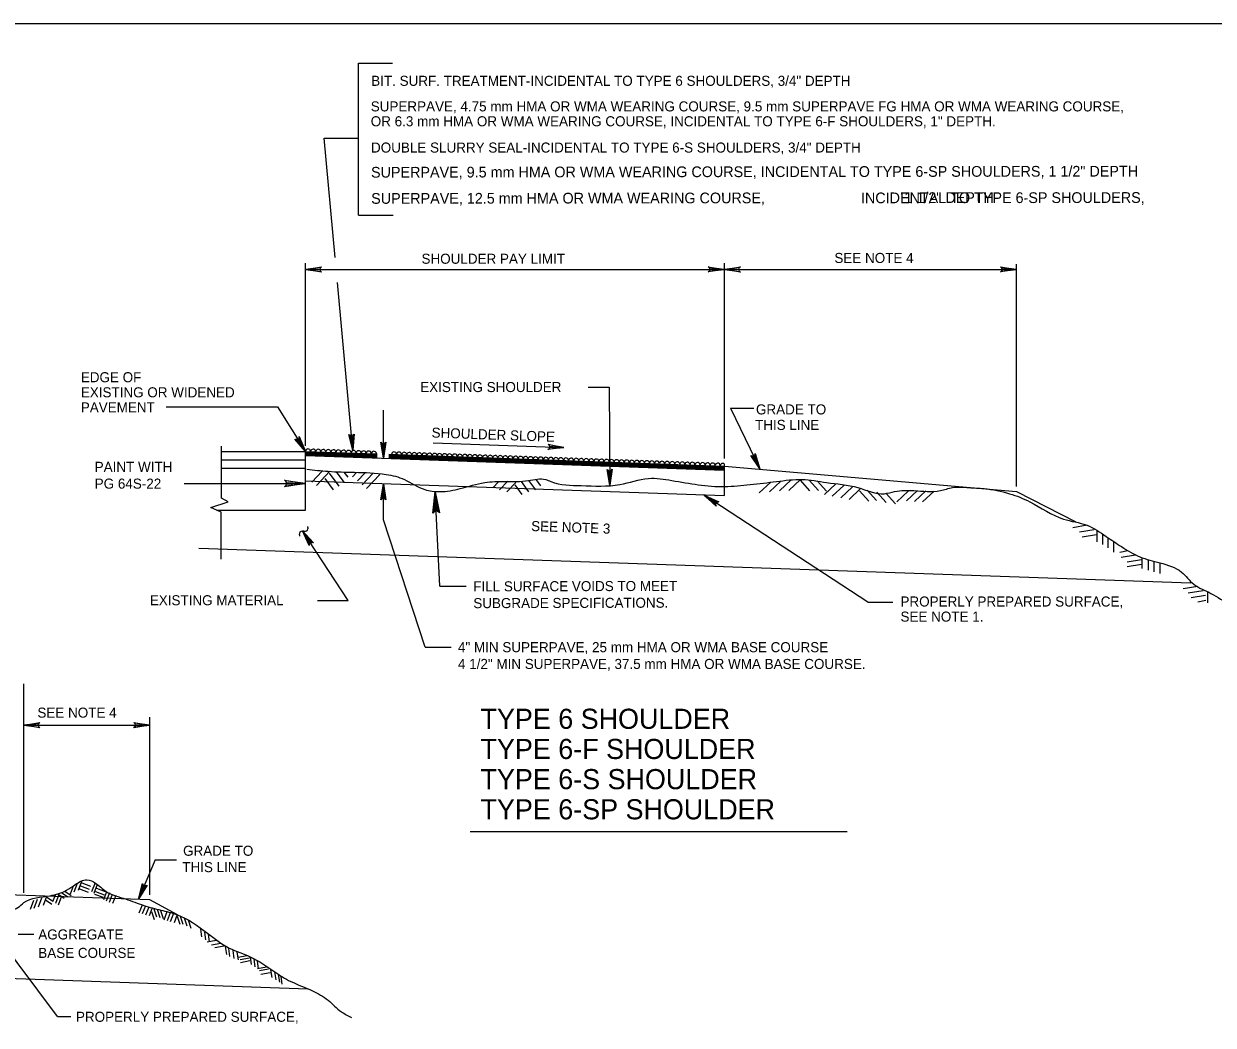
# Model space of a CAD drawing. Extents: x 638216 to 639962, y 297510 to 299292.
# Drawn here: x 638435.2 to 638790, y 298384.5 to 298683.2 of the extents above; entities that cross this region are included whole.
import ezdxf

# ---------------------------------------------------------------- set-up
doc = ezdxf.new("R2010")
doc.units = 0
for name, color, linetype in [('1', 7, 'Continuous'), ('2', 7, 'Continuous'), ('3', 7, 'Continuous')]:
    doc.layers.add(name, color=color, linetype=linetype)

msp = doc.modelspace()

# ---------------------------------------------------------------- linework, layer by layer
at = {"layer": '1'}
for points in [[(639041.88, 298119.24), (639041.88, 298683.24), (638255.88, 298683.24), (638255.88, 298119.24), (639041.88, 298119.24), (639041.88, 298145.6), (638841.88, 298145.6), (638841.88, 298210.28), (639041.88, 298210.28), (639041.88, 298239.24), (638841.88, 298239.24), (638841.88, 298119.24), (638920.69, 298119.24), (638920.69, 298145.6), (638920.69, 298119.24), (638997.69, 298119.24), (638997.69, 298145.6), (638997.69, 298133.28), (639041.88, 298133.28)], [(639041.88, 298119.24), (639041.88, 298683.24), (638255.88, 298683.24), (638255.88, 298119.24), (639041.88, 298119.24), (639041.88, 298145.6), (638841.88, 298145.6), (638841.88, 298210.28), (639041.88, 298210.28), (639041.88, 298239.24), (638841.88, 298239.24), (638841.88, 298119.24), (638920.69, 298119.24), (638920.69, 298145.6), (638920.69, 298119.24), (638997.69, 298119.24), (638997.69, 298145.6), (638997.69, 298133.28), (639041.88, 298133.28)], [(638513.28, 298546.86), (638513.5, 298546.43), (638519.27, 298546.11), (638513.28, 298546.86), (638512.97, 298547.13), (638519.27, 298546.11), (638513.5, 298545.83), (638513.29, 298545.4), (638519.27, 298546.11), (638512.97, 298545.11), (638513.29, 298545.4)], [(638557.48, 298537.59), (638557.9, 298537.84), (638557.93, 298543.62), (638557.48, 298537.59), (638557.23, 298537.27), (638557.93, 298543.62), (638558.5, 298537.87), (638558.94, 298537.69), (638557.93, 298543.62), (638559.25, 298537.38), (638558.94, 298537.69)]]:
    msp.add_lwpolyline(points, dxfattribs=at)
at = {"layer": '2'}
for p, q in [((638535.05, 298626.15), (638535.05, 298671.46)), ((638535.05, 298671.46), (638545.24, 298671.46)), ((638524.82, 298649.13), (638535.05, 298649.13)), ((638528.1, 298613.48), (638524.82, 298649.13)), ((638535.05, 298626.15), (638545.43, 298626.15)), ((638519.27, 298557.32), (638519.27, 298611.79)), ((638519.27, 298609.96), (638644.18, 298609.96)), ((638644.2, 298553.53), (638644.2, 298611.85)), ((638644.2, 298609.96), (638731.36, 298609.96)), ((638731.36, 298545.18), (638731.36, 298611.57)), ((638533.4, 298556.03), (638528.78, 298606.11)), ((638603.56, 298574.82), (638609.79, 298574.82)), ((638609.79, 298574.82), (638610.07, 298545.57)), ((638477.72, 298568.99), (638510.86, 298568.99)), ((638510.86, 298568.99), (638519.27, 298555.68)), ((638542.49, 298553.62), (638542.49, 298568.01)), ((638646.01, 298568.53), (638653, 298568.53)), ((638646.01, 298568.53), (638654.83, 298550.46)), ((638494.19, 298541.7), (638494.19, 298557.23)), ((638557.37, 298558.26), (638596.36, 298556.87)), ((638494.27, 298555.68), (638519.27, 298555.68)), ((638494.27, 298553.18), (638519.27, 298553.18)), ((638519.24, 298554.7), (638540.67, 298553.96)), ((638519.24, 298554.63), (638540.67, 298553.88)), ((638519.24, 298554.55), (638540.67, 298553.8)), ((638519.24, 298554.43), (638644.15, 298550.07)), ((638519.27, 298538.18), (638519.27, 298555.68)), ((638519.27, 298555.68), (638540.67, 298554.93)), ((638519.28, 298554.83), (638540.67, 298554.09)), ((638519.28, 298554.73), (638540.67, 298553.98)), ((638519.3, 298554.93), (638540.67, 298554.19)), ((638519.33, 298555.54), (638540.67, 298554.79)), ((638519.33, 298555.46), (638540.67, 298554.72)), ((638519.33, 298555.39), (638540.67, 298554.64)), ((638519.33, 298555.24), (638540.67, 298554.49)), ((638519.33, 298555.21), (638540.67, 298554.47)), ((638519.33, 298555.13), (638540.67, 298554.39)), ((638519.33, 298555.06), (638540.67, 298554.31)), ((638544.04, 298553.69), (638644.1, 298550.19)), ((638544.08, 298554.81), (638644.2, 298551.31)), ((638544.08, 298554.67), (638644.25, 298551.18)), ((638544.08, 298554.6), (638644.25, 298551.1)), ((638544.08, 298554.52), (638644.25, 298551.03)), ((638544.08, 298554.37), (638644.25, 298550.87)), ((638544.08, 298554.35), (638644.25, 298550.85)), ((638544.08, 298554.27), (638644.25, 298550.77)), ((638544.08, 298554.19), (638644.25, 298550.7)), ((638544.08, 298554.07), (638644.23, 298550.57)), ((638544.08, 298553.97), (638644.2, 298550.47)), ((638544.08, 298553.86), (638644.2, 298550.37)), ((638544.08, 298553.84), (638644.15, 298550.34)), ((638544.08, 298553.76), (638644.15, 298550.27)), ((638494.27, 298550.68), (638519.27, 298550.68)), ((638524.26, 298549.82), (638521.17, 298546.55)), ((638526.51, 298549.74), (638522.53, 298545.54)), ((638526.35, 298549.21), (638529.19, 298545.35)), ((638528.45, 298549.54), (638530.68, 298546.51)), ((638530.71, 298549.53), (638531.86, 298547.97)), ((638534.37, 298549.3), (638533.23, 298548.1)), ((638537, 298549.22), (638534.78, 298546.88)), ((638644.2, 298551.31), (638644.2, 298551.92)), ((638644.2, 298542.56), (638644.2, 298551.31)), ((638644.2, 298551.31), (638731.36, 298543.69)), ((638483.09, 298546.11), (638519.27, 298546.11)), ((638519.26, 298546.92), (638644.2, 298542.56)), ((638525.02, 298547.64), (638527.55, 298544.21)), ((638539.36, 298549.07), (638536.19, 298545.73)), ((638541.46, 298548.79), (638537.48, 298544.59)), ((638542.49, 298535.26), (638542.49, 298546.03)), ((638576.91, 298546.72), (638575.1, 298544.81)), ((638579.58, 298546.82), (638577.14, 298544.24)), ((638581.98, 298546.42), (638579.36, 298543.66)), ((638581.65, 298545.67), (638583.74, 298542.82)), ((638583.54, 298546.68), (638585.78, 298543.64)), ((638585.78, 298547.04), (638587.87, 298544.19)), ((638588.05, 298547.16), (638589.37, 298545.37)), ((638658.06, 298546.52), (638654.6, 298543.29)), ((638661.08, 298546.85), (638657.62, 298543.62)), ((638664.16, 298547.18), (638660.7, 298543.94)), ((638666.93, 298547.29), (638663.47, 298544.05)), ((638666.81, 298547.06), (638669.61, 298543.95)), ((638669.46, 298547.11), (638672.26, 298544)), ((638671.87, 298546.88), (638674.67, 298543.77)), ((638677.31, 298545.9), (638674.03, 298542.84)), ((638559.36, 298515.52), (638557.93, 298543.62)), ((638687, 298510.73), (638638.18, 298542.65)), ((638679.84, 298545.52), (638676.38, 298542.29)), ((638682.4, 298545.07), (638678.94, 298541.83)), ((638684.85, 298544.61), (638681.39, 298541.38)), ((638684.52, 298543.93), (638687.32, 298540.82)), ((638686.78, 298544.16), (638689.58, 298541.05)), ((638689.72, 298543.51), (638692.52, 298540.4)), ((638692.48, 298543.15), (638695.29, 298540.05)), ((638699.07, 298543.82), (638695.61, 298540.59)), ((638701.83, 298544.02), (638698.54, 298540.95)), ((638704.35, 298543.95), (638700.89, 298540.72)), ((638706.8, 298543.85), (638703.34, 298540.62)), ((638731.36, 298543.69), (638749.09, 298534.67)), ((638492.67, 298538.18), (638519.27, 298538.18)), ((638494.12, 298523.51), (638494.12, 298537.55)), ((638554.92, 298497.31), (638542.49, 298535.26)), ((638531.96, 298511.18), (638518.35, 298531.99)), ((638752.48, 298533.64), (638748.18, 298532.93)), ((638754.47, 298532.32), (638750.17, 298531.62)), ((638755.29, 298531.85), (638755.29, 298528.74)), ((638755.19, 298530.78), (638750.89, 298530.07)), ((638757.04, 298531.01), (638757.04, 298527.9)), ((638758.58, 298530.04), (638758.58, 298526.93)), ((638760.27, 298528.71), (638760.27, 298525.6)), ((638487.47, 298526.79), (638783.31, 298516.46)), ((638762.17, 298525.62), (638764.57, 298526.11)), ((638766.87, 298524.77), (638762.57, 298524.07)), ((638768.65, 298521.91), (638764.35, 298521.21)), ((638768.67, 298523.32), (638764.37, 298522.61)), ((638768.78, 298523.82), (638768.78, 298520.71)), ((638770.58, 298523.39), (638770.58, 298520.28)), ((638772.29, 298522.82), (638772.29, 298519.71)), ((638774.09, 298522.37), (638774.09, 298519.27)), ((638559.36, 298515.52), (638567.16, 298515.52)), ((638785.4, 298515.42), (638781.1, 298514.72)), ((638787.07, 298514.09), (638782.57, 298513.36)), ((638788.33, 298513.8), (638788.33, 298510.53)), ((638522.88, 298511.18), (638531.96, 298511.18)), ((638687, 298510.73), (638694.44, 298510.73)), ((638787.71, 298512.74), (638783.41, 298512.03)), ((638785.47, 298510.83), (638787.86, 298511.32)), ((638554.92, 298497.31), (638562.72, 298497.31)), ((638435.23, 298424.01), (638435.23, 298486.38)), ((638472.83, 298423.43), (638472.83, 298476.36)), ((638435.23, 298474.02), (638472.81, 298474.02)), ((638568.35, 298442.28), (638680.79, 298442.28)), ((638474.43, 298433.88), (638469.47, 298422.14)), ((638474.43, 298433.88), (638480.77, 298433.88)), ((638449.96, 298426.01), (638449.04, 298423.59)), ((638451.17, 298426.83), (638450.16, 298424.15)), ((638452.41, 298427.4), (638451.39, 298424.72)), ((638451.88, 298425.17), (638454.45, 298424.22)), ((638452.13, 298426.06), (638454.7, 298425.11)), ((638452.58, 298426.98), (638455.16, 298426.02)), ((638456.46, 298427.01), (638455.45, 298424.33)), ((638457.14, 298426.48), (638456.12, 298423.8)), ((638456.92, 298425.35), (638459.5, 298424.4)), ((638408.83, 298424.26), (638472.68, 298422.03)), ((638438.1, 298421.67), (638437.08, 298418.99)), ((638439.19, 298422.06), (638438.18, 298419.37)), ((638440.5, 298422.41), (638439.48, 298419.73)), ((638441.98, 298422.91), (638440.96, 298420.22)), ((638441.69, 298421.95), (638443.56, 298420.63)), ((638442.02, 298422.8), (638443.89, 298421.49)), ((638444.65, 298423.47), (638443.82, 298421.29)), ((638445.65, 298423.55), (638444.63, 298420.86)), ((638445.4, 298423.71), (638447.27, 298422.39)), ((638446.51, 298422.97), (638445.49, 298420.29)), ((638446.45, 298424.14), (638448.32, 298422.82)), ((638447.5, 298424.47), (638449.36, 298423.16)), ((638456.32, 298423.62), (638458.9, 298422.67)), ((638456.61, 298424.4), (638459.18, 298423.45)), ((638459.89, 298424.31), (638458.97, 298421.87)), ((638460.76, 298423.96), (638459.83, 298421.52)), ((638461.62, 298423.51), (638460.7, 298421.07)), ((638462.65, 298423.25), (638461.72, 298420.81)), ((638472.68, 298422.03), (638480.95, 298417.49)), ((638470.5, 298420.35), (638469.57, 298417.91)), ((638471.49, 298420.12), (638470.57, 298417.69)), ((638472.49, 298419.77), (638471.56, 298417.33)), ((638473.54, 298419.55), (638472.62, 298417.11)), ((638473.32, 298418.42), (638474.09, 298416.02)), ((638474.01, 298419.24), (638474.78, 298416.84)), ((638475.03, 298419.08), (638475.8, 298416.68)), ((638476.03, 298418.73), (638476.8, 298416.33)), ((638477.92, 298418.33), (638476.99, 298415.89)), ((638478.91, 298418.06), (638477.98, 298415.62)), ((638445.25, 298387.11), (638423.56, 298416.16)), ((638479.84, 298417.8), (638478.92, 298415.36)), ((638480.95, 298417.49), (638480.03, 298415.06)), ((638480.95, 298417.01), (638481.72, 298414.61)), ((638481.88, 298417.08), (638482.65, 298414.67)), ((638483.09, 298416.56), (638483.86, 298414.16)), ((638484.26, 298415.9), (638485.03, 298413.49)), ((638433.58, 298411.66), (638438.18, 298411.66)), ((638487.89, 298413.17), (638488.24, 298410.85)), ((638489.09, 298412.29), (638489.44, 298409.97)), ((638490.18, 298411.69), (638490.53, 298409.37)), ((638492.65, 298409.82), (638489.9, 298409.29)), ((638493.99, 298408.91), (638491.24, 298408.38)), ((638494.98, 298408.1), (638492.23, 298407.57)), ((638495.29, 298407.95), (638495.65, 298405.63)), ((638496.25, 298407.36), (638496.6, 298405.03)), ((638497.55, 298406.79), (638497.9, 298404.46)), ((638498.78, 298406.33), (638499.14, 298404)), ((638501.85, 298405.24), (638499.1, 298404.71)), ((638502.52, 298404.53), (638499.77, 298404.01)), ((638502.74, 298404.92), (638503.09, 298402.59)), ((638503.83, 298404.25), (638504.18, 298401.92)), ((638335.27, 298401.82), (638519.95, 298395.37)), ((638502.63, 298403.69), (638499.88, 298403.16)), ((638504.82, 298403.62), (638505.17, 298401.29)), ((638507.64, 298401.82), (638504.89, 298401.29)), ((638508.24, 298401.22), (638505.49, 298400.69)), ((638508.84, 298401.04), (638509.19, 298398.71)), ((638510, 298400.41), (638510.36, 298398.08)), ((638508.7, 298400.16), (638505.95, 298399.63)), ((638511.13, 298399.66), (638511.48, 298397.34)), ((638511.87, 298399.07), (638512.22, 298396.74)), ((638445.25, 298387.11), (638449.27, 298387.11))]:
    msp.add_line(p, q, dxfattribs=at)
for points in [[(638523.81, 298609.39), (638523.64, 298609.72), (638519.27, 298609.96), (638523.81, 298609.39), (638524.05, 298609.19), (638519.27, 298609.96), (638523.64, 298610.18), (638523.8, 298610.5), (638519.27, 298609.96), (638524.05, 298610.72), (638523.8, 298610.5)], [(638639.64, 298610.53), (638639.81, 298610.2), (638644.18, 298609.96), (638639.64, 298610.53), (638639.4, 298610.73), (638644.18, 298609.96), (638639.81, 298609.74), (638639.65, 298609.42), (638644.18, 298609.96), (638639.4, 298609.2), (638639.65, 298609.42)], [(638648.74, 298609.39), (638648.57, 298609.72), (638644.2, 298609.96), (638648.74, 298609.39), (638648.97, 298609.19), (638644.2, 298609.96), (638648.56, 298610.18), (638648.72, 298610.5), (638644.2, 298609.96), (638648.97, 298610.72), (638648.72, 298610.5)], [(638726.82, 298610.53), (638726.99, 298610.2), (638731.36, 298609.96), (638726.82, 298610.53), (638726.59, 298610.73), (638731.36, 298609.96), (638727, 298609.74), (638726.84, 298609.42), (638731.36, 298609.96), (638726.59, 298609.2), (638726.84, 298609.42)], [(638517.33, 298559.82), (638517.14, 298559.5), (638519.27, 298555.68), (638517.33, 298559.82), (638517.37, 298560.12), (638519.27, 298555.68), (638516.76, 298559.25), (638516.4, 298559.22), (638519.27, 298555.68), (638516.08, 298559.31), (638516.4, 298559.22)], [(638533.55, 298560.61), (638533.24, 298560.41), (638533.4, 298556.03), (638533.55, 298560.61), (638533.73, 298560.86), (638533.4, 298556.03), (638532.79, 298560.36), (638532.45, 298560.49), (638533.4, 298556.03), (638532.21, 298560.72), (638532.45, 298560.49)], [(638543.06, 298558.16), (638542.73, 298557.99), (638542.49, 298553.62), (638543.06, 298558.16), (638543.26, 298558.39), (638542.49, 298553.62), (638542.27, 298557.98), (638541.95, 298558.14), (638542.49, 298553.62), (638541.73, 298558.39), (638541.95, 298558.14)], [(638591.84, 298557.6), (638592, 298557.26), (638596.36, 298556.87), (638591.84, 298557.6), (638591.62, 298557.81), (638596.36, 298556.87), (638591.99, 298556.81), (638591.81, 298556.49), (638596.36, 298556.87), (638591.56, 298556.28), (638591.81, 298556.49)], [(638653.35, 298554.79), (638653.13, 298554.49), (638654.83, 298550.46), (638653.35, 298554.79), (638653.43, 298555.08), (638654.83, 298550.46), (638652.72, 298554.29), (638652.36, 298554.29), (638654.83, 298550.46), (638652.06, 298554.42), (638652.36, 298554.29)], [(638610.54, 298550.13), (638610.22, 298549.95), (638610.07, 298545.57), (638610.54, 298550.13), (638610.74, 298550.36), (638610.07, 298545.57), (638609.76, 298549.94), (638609.43, 298550.09), (638610.07, 298545.57), (638609.21, 298550.33), (638609.43, 298550.09)], [(638541.92, 298541.49), (638542.25, 298541.66), (638542.49, 298546.03), (638541.92, 298541.49), (638541.72, 298541.26), (638542.49, 298546.03), (638542.7, 298541.67), (638543.03, 298541.51), (638542.49, 298546.03), (638543.25, 298541.26), (638543.03, 298541.51)], [(638641.67, 298539.69), (638641.7, 298540.05), (638638.18, 298542.65), (638641.67, 298539.69), (638641.75, 298539.39), (638638.18, 298542.65), (638641.95, 298540.44), (638642.26, 298540.62), (638638.18, 298542.65), (638642.59, 298540.67), (638642.26, 298540.62)], [(638494.12, 298537.55), (638491.02, 298538.9), (638496.22, 298540.63), (638494.19, 298541.7)], [(638520.36, 298527.88), (638520.54, 298528.2), (638518.35, 298531.99), (638520.36, 298527.88), (638520.32, 298527.58), (638518.35, 298531.99), (638520.92, 298528.46), (638521.28, 298528.5), (638518.35, 298531.99), (638521.6, 298528.41), (638521.28, 298528.5)], [(638439.77, 298473.45), (638439.6, 298473.78), (638435.23, 298474.02), (638439.77, 298473.45), (638440, 298473.25), (638435.23, 298474.02), (638439.59, 298474.24), (638439.75, 298474.56), (638435.23, 298474.02), (638440, 298474.78), (638439.75, 298474.56)], [(638468.27, 298474.59), (638468.44, 298474.26), (638472.81, 298474.02), (638468.27, 298474.59), (638468.03, 298474.79), (638472.81, 298474.02), (638468.44, 298473.81), (638468.28, 298473.48), (638472.81, 298474.02), (638468.03, 298473.26), (638468.28, 298473.48)], [(638471.77, 298426.1), (638471.4, 298426.07), (638469.47, 298422.14), (638471.77, 298426.1), (638472.04, 298426.24), (638469.47, 298422.14), (638470.97, 298426.24), (638470.74, 298426.52), (638469.47, 298422.14), (638470.63, 298426.83), (638470.74, 298426.52)]]:
    msp.add_lwpolyline(points, dxfattribs=at)
for centre, start in [((638520.02, 298555.65), 8.6519), ((638521.53, 298555.6), 8.6519), ((638523.04, 298555.55), 8.6519), ((638524.55, 298555.5), 8.6519), ((638526.06, 298555.44), 8.6519), ((638527.57, 298555.39), 8.6519), ((638529.08, 298555.34), 8.6519), ((638530.59, 298555.29), 8.6519), ((638532.09, 298555.23), 8.6519), ((638533.6, 298555.18), 8.6519), ((638535.11, 298555.13), 8.6519), ((638536.62, 298555.07), 8.6519), ((638538.13, 298555.02), 8.6519), ((638539.64, 298554.97), 8.6519), ((638545.67, 298554.76), 8.6519), ((638547.18, 298554.71), 8.6519), ((638548.69, 298554.65), 8.6519), ((638550.2, 298554.6), 8.6519), ((638551.71, 298554.55), 8.6519), ((638553.22, 298554.5), 8.6519), ((638554.73, 298554.44), 8.6519), ((638556.24, 298554.39), 8.6519), ((638557.74, 298554.34), 8.6519), ((638559.25, 298554.28), 8.6519), ((638560.76, 298554.23), 8.6519), ((638562.27, 298554.18), 8.6519), ((638563.78, 298554.13), 8.6519), ((638565.29, 298554.07), 8.6519), ((638566.8, 298554.02), 8.6519), ((638568.31, 298553.97), 8.6519), ((638569.81, 298553.92), 8.6519), ((638571.32, 298553.86), 8.6519), ((638572.83, 298553.81), 8.6519), ((638574.34, 298553.76), 8.6519), ((638575.85, 298553.7), 8.6519), ((638577.36, 298553.65), 8.6519), ((638578.87, 298553.6), 8.6519), ((638580.38, 298553.55), 8.6519), ((638581.89, 298553.49), 8.6519), ((638583.39, 298553.44), 8.6519), ((638584.9, 298553.39), 8.6519), ((638586.41, 298553.34), 8.6519), ((638587.92, 298553.28), 8.6519), ((638589.43, 298553.23), 8.6519), ((638590.94, 298553.18), 8.6519), ((638592.45, 298553.13), 8.6519), ((638593.96, 298553.07), 8.6519), ((638595.46, 298553.02), 8.6519), ((638596.97, 298552.97), 8.6519), ((638598.48, 298552.91), 8.6519), ((638599.99, 298552.86), 8.6519), ((638601.5, 298552.81), 8.6519), ((638603.01, 298552.76), 8.6519), ((638604.52, 298552.7), 8.6519), ((638606.03, 298552.65), 8.6519), ((638607.54, 298552.6), 8.6519), ((638609.04, 298552.55), 8.6519), ((638610.55, 298552.49), 8.6519), ((638612.06, 298552.44), 8.6519), ((638613.57, 298552.39), 8.6519), ((638615.08, 298552.34), 8.6519), ((638616.59, 298552.28), 8.6519), ((638618.1, 298552.23), 8.6519), ((638619.59, 298552.19), 8.6519), ((638621.1, 298552.14), 8.6519), ((638622.6, 298552.08), 8.6519), ((638624.11, 298552.03), 8.6519), ((638625.62, 298551.98), 8.6519), ((638627.13, 298551.93), 8.6519), ((638628.64, 298551.87), 8.6519), ((638630.15, 298551.82), 8.6519), ((638631.66, 298551.77), 8.6519), ((638633.17, 298551.71), 8.6519), ((638634.67, 298551.66), 8.6519), ((638636.18, 298551.61), 8.6519), ((638637.69, 298551.56), 8.6519), ((638639.2, 298551.5), 8.6519), ((638640.71, 298551.45), 8.6519), ((638642.22, 298551.4), 8.6519), ((638643.73, 298551.35), 49.64)]:
    msp.add_arc(centre, 0.762, start, 176.7199, dxfattribs=at)
for points in [[(638519.61, 298550.35), (638525.98, 298549.74), (638533.86, 298549.44), (638543.29, 298548.83), (638548.74, 298547.31), (638554.81, 298544.28), (638559.36, 298543.68), (638565.42, 298544.59), (638572.72, 298546.4), (638578.78, 298546.71), (638585.76, 298547.01), (638590.91, 298547.31), (638592.43, 298546.71), (638601.52, 298545.49), (638613.07, 298545.8), (638621.56, 298547.62), (638628.53, 298547.01), (638644.32, 298545.19), (638651.9, 298545.8), (638659.78, 298546.71), (638667.39, 298547.31), (638674.66, 298546.4), (638684.06, 298544.89), (638691.95, 298543.07), (638695, 298543.68), (638700.76, 298543.98), (638708.65, 298543.98), (638712.28, 298544.89), (638717.14, 298544.89), (638721.68, 298544.59), (638729.29, 298543.07), (638735.35, 298540.64), (638745.36, 298535.49), (638752.33, 298533.67), (638758.11, 298530.31), (638762.66, 298527.28), (638768.12, 298524.25), (638774.18, 298522.43), (638780.55, 298519.7), (638784.21, 298516.06), (638789.37, 298513.33), (638795.13, 298510.3), (638795.24, 298510.27)], [(638517.6, 298530.38), (638517.51, 298530.85), (638517.69, 298531.67), (638518.35, 298531.99), (638518.89, 298531.9), (638519.52, 298532.01), (638519.99, 298532.54), (638520.03, 298532.82), (638519.92, 298533.27)], [(638429.45, 298418.28), (638433.43, 298419.58), (638435.26, 298421.09), (638443.05, 298423.14), (638447.99, 298424.77), (638450.59, 298426.47), (638454.05, 298427.88), (638456.61, 298426.92), (638459.76, 298424.42), (638465.59, 298422.17), (638471.04, 298420.25), (638476.11, 298418.84), (638480.76, 298417.56), (638490.03, 298411.95), (638496.5, 298407.52), (638502.76, 298404.92), (638510.1, 298400.4), (638514.84, 298397.58), (638521.32, 298394.79), (638525.97, 298391.97), (638529.95, 298388.54), (638532.96, 298386.81)]]:
    msp.add_spline(points, degree=3, dxfattribs=at)

# ---------------------------------------------------------------- texts
at = {"layer": '3'}
for s, height, p in [('BIT. SURF. TREATMENT-INCIDENTAL TO TYPE 6 SHOULDERS, 3/4" DEPTH', 3, (638538.86, 298664.73)), ('SUPERPAVE, 4.75 mm HMA OR WMA WEARING COURSE, 9.5 mm SUPERPAVE FG HMA OR WMA WEARING COURSE,', 3, (638538.72, 298657.1)), ('OR 6.3 mm HMA OR WMA WEARING COURSE, INCIDENTAL TO TYPE 6-F SHOULDERS, 1" DEPTH.', 3, (638538.72, 298652.66)), ('DOUBLE SLURRY SEAL-INCIDENTAL TO TYPE 6-S SHOULDERS, 3/4" DEPTH', 3, (638538.8, 298644.82)), ('SHOULDER PAY LIMIT', 3, (638553.86, 298611.65)), ('SEE NOTE 4', 3, (638677.03, 298611.89)), ('EDGE OF', 3, (638452.23, 298576.31)), ('EXISTING OR WIDENED', 3, (638452.23, 298571.81)), ('EXISTING SHOULDER', 3, (638553.47, 298573.38)), ('PAVEMENT', 3, (638452.23, 298567.31)), ('GRADE TO ', 3, (638653.64, 298566.71)), ('THIS LINE', 3, (638653.35, 298562.09)), ('PAINT WITH', 3, (638456.37, 298549.57)), ('PG 64S-22', 3, (638456.37, 298544.57)), ('EXISTING MATERIAL', 3, (638472.81, 298509.78)), ('PROPERLY PREPARED SURFACE,', 3, (638696.74, 298509.4)), ('SEE NOTE 1.', 3, (638696.74, 298504.9)), ('4" MIN SUPERPAVE, 25 mm HMA OR WMA BASE COURSE', 3, (638564.74, 298495.78)), ('4 1/2" MIN SUPERPAVE, 37.5 mm HMA OR WMA BASE COURSE. ', 3, (638564.74, 298490.78)), ('SEE NOTE 4', 3, (638439.28, 298476.25)), ('TYPE 6 SHOULDER', 6, (638571.47, 298472.92)), ('TYPE 6-F SHOULDER', 6, (638571.47, 298463.92)), ('TYPE 6-S SHOULDER', 6, (638571.47, 298454.92)), ('TYPE 6-SP SHOULDER', 6, (638571.47, 298445.92)), ('GRADE TO ', 3, (638482.73, 298435.05)), ('THIS LINE', 3, (638482.49, 298430.17)), ('AGGREGATE ', 3, (638439.53, 298410.09)), ('BASE COURSE', 3, (638439.53, 298404.59)), ('PROPERLY PREPARED SURFACE,', 3, (638450.78, 298385.52))]:
    msp.add_text(s, height=height, dxfattribs=at).set_placement(p)
for s, height, rotation, p in [('SUPERPAVE, 9.5 mm HMA OR WMA WEARING COURSE, INCIDENTAL TO TYPE 6-SP SHOULDERS, 1 1/2" DEPTH', 3.1998, 0.0819, (638538.8, 298637.35)), ('SUPERPAVE, 12.5 mm HMA OR WMA WEARING COURSE,                                   1 1/2" DEPTH', 3.1998, 0.0819, (638538.85, 298629.54)), ('INCIDENTAL TO TYPE 6-SP SHOULDERS,', 3.1998, 0.0819, (638684.95, 298629.7)), ('SHOULDER SLOPE', 3, 357.9999, (638556.83, 298559.82)), ('SEE NOTE 3', 3, 357.9999, (638586.52, 298531.94)), ('FILL SURFACE VOIDS TO MEET', 3, 0.1408, (638569.29, 298513.91)), ('SUBGRADE SPECIFICATIONS.', 3, 0.1408, (638569.31, 298508.91))]:
    msp.add_text(s, height=height, rotation=rotation, dxfattribs=at).set_placement(p)

doc.saveas('drawing.dxf')
